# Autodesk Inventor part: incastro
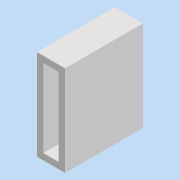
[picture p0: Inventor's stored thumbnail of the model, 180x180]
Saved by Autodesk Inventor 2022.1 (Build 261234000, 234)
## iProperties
Created: 2022-02
Part Number: incastro
Material: Generico
Document SubType Name: Modeling
Designer: i911900
Density: 1 g/cm^3
Appearance: Default
Author: i911900
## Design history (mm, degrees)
sketch "Schizzo1"
  geometry: L1 (-2, 0)-(-2, -10) reference; L2 (0, -10)-(-2, -10) reference; L3 (0, -10)-(0, 0) reference; L4 (0, 0)-(-2, 0) reference; L5 (0.807, 0.807)-(0.807, -10.807); L6 (0.807, -10.807)-(-2.807, -10.807); L7 (-2.807, -10.807)-(-2.807, 0.807); L8 (-2.807, 0.807)-(0.807, 0.807)
  constraints: 8 end point, 3 other
extrude "Estrusione1" new body sketch "Schizzo1" distance "d0" = 10; taper "d1" = 0 deg
node "Solido1"
node "Riferimento1"
